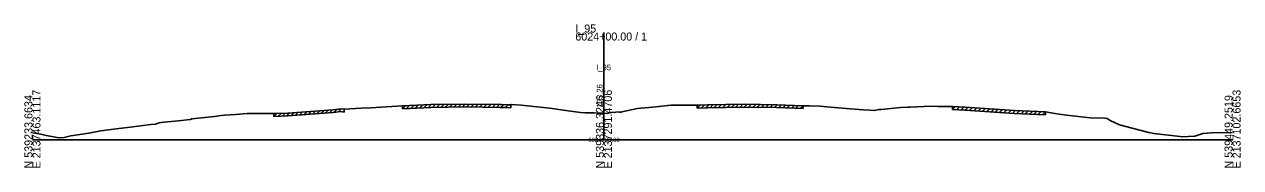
# Model space of a CAD drawing. Extents: x -12534 to 3403, y -1332 to 21983.
# Drawn here: x 997.2 to 1422.8, y 13490.3 to 13540.3 of the extents above; entities that cross this region are included whole.
import ezdxf

# ---------------------------------------------------------------- set-up
doc = ezdxf.new("R2010")
doc.units = 0
for name, color, linetype in [('RD_GPK_XS_Cell', 7, 'Continuous'), ('RD_XS_ExGround', 7, 'Continuous'), ('RD_XS_ExPaveRet', 7, 'Continuous'), ('RD_XS_TX_Baseline', 7, 'Continuous'), ('RD_XS_TX_Elev_EX', 7, 'Continuous'), ('RD_XS_TX_Station', 7, 'Continuous')]:
    doc.layers.add(name, color=color, linetype=linetype)

msp = doc.modelspace()

# ---------------------------------------------------------------- linework, layer by layer
at = {"layer": 'RD_GPK_XS_Cell'}
for p, q in [((1200, 13500), (1200, 13537.46)), ((1000, 13500), (1200, 13500)), ((1200, 13500), (1420, 13500))]:
    msp.add_line(p, q, dxfattribs=at)
at = {"layer": 'RD_XS_ExGround'}
msp.add_lwpolyline([(1000, 13502.45), (1002.88, 13501.96), (1004.85, 13501.53), (1009.36, 13500.71), (1011.07, 13500.86), (1013.48, 13501.42), (1019.7, 13502.33), (1023.97, 13503.11), (1029.28, 13503.89), (1034.19, 13504.4), (1041.38, 13505.35), (1043.03, 13505.52), (1044.36, 13505.93), (1045.08, 13506.05), (1052.19, 13506.78), (1054.1, 13507), (1055.34, 13507.12), (1055.83, 13507.32), (1063.72, 13508.18), (1066.1, 13508.47), (1067.27, 13508.57), (1071.03, 13508.84), (1075.19, 13509.14), (1084.46, 13509.15), (1089.35, 13509.34), (1105.21, 13510.49), (1107.88, 13510.86), (1109.09, 13510.68), (1115.02, 13511.01), (1118.46, 13511.19), (1123.87, 13511.48), (1129.46, 13511.82), (1139.43, 13512.28), (1151.34, 13512.49), (1163.63, 13512.29), (1164.13, 13512.32), (1166.11, 13512.26), (1167.46, 13512.21), (1167.65, 13512.33), (1171, 13512.15), (1181.04, 13511.09), (1186.7, 13510.23), (1191.79, 13509.53), (1193.45, 13509.37), (1196.63, 13509.4), (1197.92, 13509.35), (1200, 13509.26), (1200.98, 13509.21), (1202.34, 13509.55), (1202.71, 13509.57), (1205.51, 13509.75), (1205.55, 13509.59), (1206.29, 13509.81), (1211.77, 13510.91), (1212.9, 13511.06), (1217.11, 13511.45), (1223.43, 13512.14), (1230.54, 13512.09), (1232.63, 13512.1), (1236.29, 13512.22), (1249.07, 13512.44), (1260.56, 13512.25), (1269.74, 13511.91), (1271.95, 13511.86), (1275.66, 13511.76), (1278.01, 13511.53), (1286.18, 13510.85), (1290.83, 13510.48), (1293.07, 13510.31), (1294.71, 13510.23), (1296.16, 13510.54), (1297.05, 13510.58), (1303.84, 13511.24), (1306.37, 13511.39), (1307.13, 13511.43), (1314.27, 13511.7), (1316.97, 13511.68), (1321.97, 13511.62), (1326.35, 13511.37), (1343.65, 13510.2), (1354.5, 13509.75), (1357.82, 13509.21), (1359.34, 13508.93), (1361.94, 13508.6), (1370.21, 13507.71), (1375.33, 13507.59), (1376.13, 13507.46), (1377.19, 13506.74), (1380.47, 13505.22), (1384.88, 13504.09), (1390.66, 13502.61), (1392.41, 13502.18), (1401.65, 13501.12), (1402.36, 13501.07), (1406.77, 13501.24), (1409.58, 13502.19), (1412.59, 13502.47), (1420, 13502.56)], dxfattribs=at)
at = {"layer": 'RD_XS_ExPaveRet'}
for p, q in [((1129.46, 13510.82), (1130.51, 13511.87)), ((1129.46, 13510.82), (1129.46, 13511.82)), ((1129.46, 13510.82), (1139.43, 13511.28)), ((1130.96, 13510.89), (1132.01, 13511.94)), ((1132.46, 13510.96), (1133.51, 13512.01)), ((1133.96, 13511.03), (1135.01, 13512.08)), ((1135.46, 13511.1), (1136.51, 13512.15)), ((1136.96, 13511.17), (1138.01, 13512.21)), ((1138.46, 13511.23), (1139.5, 13512.28)), ((1139.43, 13511.28), (1151.34, 13511.49)), ((1139.96, 13511.29), (1140.98, 13512.31)), ((1141.46, 13511.31), (1142.48, 13512.33)), ((1142.96, 13511.34), (1143.98, 13512.36)), ((1144.46, 13511.37), (1145.48, 13512.38)), ((1145.96, 13511.39), (1146.98, 13512.41)), ((1147.46, 13511.42), (1148.48, 13512.44)), ((1148.96, 13511.44), (1149.98, 13512.46)), ((1150.46, 13511.47), (1151.47, 13512.48)), ((1151.34, 13511.49), (1163.63, 13511.29)), ((1151.96, 13511.48), (1152.94, 13512.46)), ((1153.46, 13511.45), (1154.44, 13512.44)), ((1154.96, 13511.43), (1155.94, 13512.41)), ((1156.46, 13511.4), (1157.44, 13512.39)), ((1157.96, 13511.38), (1158.94, 13512.36)), ((1159.46, 13511.36), (1160.44, 13512.34)), ((1160.96, 13511.33), (1161.94, 13512.32)), ((1162.46, 13511.31), (1163.44, 13512.29)), ((1163.63, 13511.29), (1164.13, 13511.32)), ((1163.96, 13511.31), (1164.94, 13512.29)), ((1164.13, 13511.32), (1166.11, 13511.26)), ((1165.46, 13511.28), (1166.43, 13512.25)), ((1166.11, 13511.26), (1167.46, 13511.21)), ((1167.46, 13512.21), (1167.46, 13511.21)), ((1232.63, 13511.1), (1233.66, 13512.13)), ((1232.63, 13511.1), (1232.63, 13512.1)), ((1232.63, 13511.1), (1236.29, 13511.22)), ((1234.13, 13511.15), (1235.16, 13512.18)), ((1235.63, 13511.2), (1236.66, 13512.23)), ((1236.29, 13511.22), (1249.07, 13511.44)), ((1237.13, 13511.23), (1238.15, 13512.25)), ((1238.63, 13511.26), (1239.65, 13512.28)), ((1240.13, 13511.29), (1241.15, 13512.3)), ((1241.63, 13511.31), (1242.65, 13512.33)), ((1243.13, 13511.34), (1244.15, 13512.36)), ((1244.63, 13511.36), (1245.65, 13512.38)), ((1246.13, 13511.39), (1247.15, 13512.41)), ((1247.63, 13511.42), (1248.65, 13512.43)), ((1249.07, 13511.44), (1260.56, 13511.25)), ((1249.13, 13511.44), (1250.11, 13512.42)), ((1250.63, 13511.42), (1251.61, 13512.4)), ((1252.13, 13511.39), (1253.11, 13512.37)), ((1253.63, 13511.37), (1254.61, 13512.35)), ((1255.13, 13511.34), (1256.11, 13512.33)), ((1256.63, 13511.32), (1257.61, 13512.3)), ((1258.13, 13511.29), (1259.11, 13512.28)), ((1259.63, 13511.27), (1260.61, 13512.25)), ((1260.56, 13511.25), (1269.74, 13510.91)), ((1261.13, 13511.23), (1262.09, 13512.19)), ((1262.63, 13511.17), (1263.59, 13512.14)), ((1264.13, 13511.12), (1265.09, 13512.08)), ((1265.63, 13511.06), (1266.59, 13512.02)), ((1267.13, 13511), (1268.09, 13511.97)), ((1268.63, 13510.95), (1269.59, 13511.91)), ((1269.74, 13511.91), (1269.74, 13510.91)), ((1321.97, 13510.62), (1321.97, 13511.62)), ((1321.97, 13510.62), (1322.91, 13511.57)), ((1323.47, 13510.54), (1324.41, 13511.48)), ((1324.97, 13510.45), (1325.91, 13511.4)), ((1326.47, 13510.36), (1327.41, 13511.3)), ((1327.97, 13510.26), (1328.91, 13511.2)), ((1084.46, 13508.15), (1085.5, 13509.19)), ((1084.46, 13508.15), (1084.46, 13509.15)), ((1084.46, 13508.15), (1089.35, 13508.34)), ((1085.96, 13508.21), (1087, 13509.25)), ((1087.46, 13508.27), (1088.5, 13509.31)), ((1088.96, 13508.33), (1090.02, 13509.39)), ((1089.35, 13508.34), (1105.21, 13509.49)), ((1090.46, 13508.42), (1091.54, 13509.5)), ((1091.96, 13508.53), (1093.04, 13509.61)), ((1093.46, 13508.64), (1094.54, 13509.72)), ((1094.96, 13508.75), (1096.04, 13509.83)), ((1096.46, 13508.86), (1097.54, 13509.94)), ((1097.96, 13508.97), (1099.04, 13510.05)), ((1099.46, 13509.08), (1100.54, 13510.15)), ((1100.96, 13509.19), (1102.04, 13510.26)), ((1102.46, 13509.29), (1103.54, 13510.37)), ((1103.96, 13509.4), (1105.04, 13510.48)), ((1105.21, 13509.49), (1107.88, 13509.86)), ((1105.46, 13509.53), (1106.62, 13510.69)), ((1106.96, 13509.73), (1108.06, 13510.83)), ((1107.88, 13509.86), (1109.09, 13509.68)), ((1109.09, 13510.68), (1109.09, 13509.68)), ((1321.97, 13510.62), (1326.35, 13510.37)), ((1326.35, 13510.37), (1343.65, 13509.2)), ((1329.47, 13510.16), (1330.41, 13511.1)), ((1330.97, 13510.06), (1331.91, 13510.99)), ((1332.47, 13509.96), (1333.41, 13510.89)), ((1333.97, 13509.85), (1334.91, 13510.79)), ((1335.47, 13509.75), (1336.41, 13510.69)), ((1336.97, 13509.65), (1337.91, 13510.59)), ((1338.47, 13509.55), (1339.41, 13510.48)), ((1339.97, 13509.45), (1340.91, 13510.38)), ((1341.47, 13509.34), (1342.41, 13510.28)), ((1342.97, 13509.24), (1343.91, 13510.19)), ((1343.65, 13509.2), (1354.5, 13508.75)), ((1344.47, 13509.16), (1345.43, 13510.12)), ((1345.97, 13509.1), (1346.93, 13510.06)), ((1347.47, 13509.04), (1348.43, 13510)), ((1348.97, 13508.98), (1349.93, 13509.94)), ((1350.47, 13508.91), (1351.43, 13509.87)), ((1351.97, 13508.85), (1352.93, 13509.81)), ((1353.47, 13508.79), (1354.43, 13509.75)), ((1354.5, 13509.75), (1354.5, 13508.75))]:
    msp.add_line(p, q, dxfattribs=at)

# ---------------------------------------------------------------- texts
at = {"layer": 'RD_GPK_XS_Cell'}
for s, p in [('6024+00.00 / 1', (1190, 13534.66)), ('I_95', (1190, 13537.46))]:
    msp.add_text(s, height=2.8, dxfattribs=at).set_placement(p)
for s, p in [('N 539233.6634', (1000, 13490)), ('E 2137463.1117', (1002.8, 13490)), ('N 539336.3246', (1200, 13490)), ('E 2137291.4706', (1202.8, 13490)), ('N 539449.2519', (1420, 13490)), ('E 2137102.6653', (1422.8, 13490))]:
    msp.add_text(s, height=2.8, rotation=90, dxfattribs=at).set_placement(p)
at = {"layer": 'RD_XS_TX_Baseline'}
msp.add_text('I_95', height=2, dxfattribs=at).set_placement((1197.28, 13524.26))
at = {"layer": 'RD_XS_TX_Elev_EX'}
msp.add_text('103.26', height=2, rotation=90, dxfattribs=at).set_placement((1199.5, 13511.26))
at = {"layer": 'RD_XS_TX_Station'}
msp.add_text('6024+00.00', height=1.5, dxfattribs=at).set_placement((1194.54, 13499.26))

doc.saveas('drawing.dxf')
